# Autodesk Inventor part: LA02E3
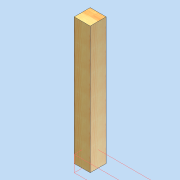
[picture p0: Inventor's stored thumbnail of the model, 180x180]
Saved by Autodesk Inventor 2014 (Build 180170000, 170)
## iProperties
Created: 2011-04
Part Number: LA02E3
Document SubType Name: Modeling
Designer: david.appleford
Density: 0.44 g/cm^3
Description: Lug End 0.5w 3 Slots
Mass: 1102.73 g
Surface Area: 1566.72 cm^2
Volume: 2506.21 cm^3
Cost Center: £6.00
Material: 000 Redwood
Appearance: Wood (Pine)
Justset: False
Author: david.appleford
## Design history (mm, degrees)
sketch "Sketch1"
  geometry: L1 (0, 0)-(68, 0); L2 (68, 0)-(68, 68); L3 (68, 68)-(0, 68); L4 (0, 68)-(0, 0)
  constraints: 8 end point, 2 parallel, 1 horizontal, 1 perpendicular
  dimensions: "d0" = 68 distance between parallel lines of L2 L4 (= t); "d1" = 68 distance between parallel lines of L1 L3 (= t)
extrude "Extrusion1" new body sketch "Sketch1" distance "d2" = 542 (= 0.5 x w - t); taper "d3" = 0 deg
body "Solid1"
other parameters: "t" = 68 [user parameter; used in 3 equation terms], "Cl" = 2 [user parameter]
